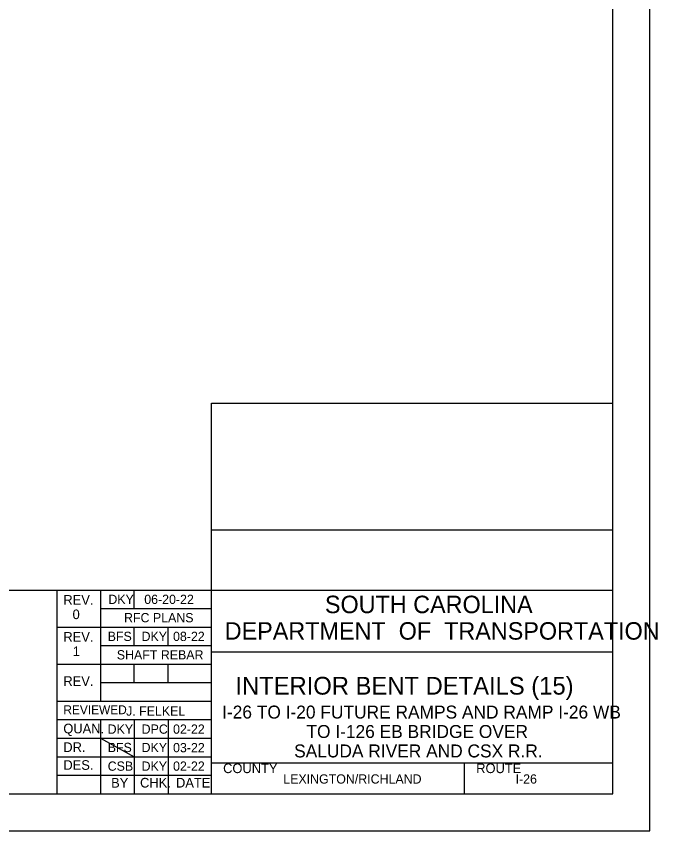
# Model space of a CAD drawing. Extents: x -149.6 to -53.3, y -21.7 to 37.
# Drawn here: x -76.41 to -53.32, y -21.66 to 7.67 of the extents above; entities that cross this region are included whole.
import ezdxf

# ---------------------------------------------------------------- set-up
doc = ezdxf.new("R2010")
doc.units = 0
for name, color, linetype in [('BR_BORDER LINES', 7, 'Continuous'), ('BR_TEXT', 7, 'Continuous'), ('Level 31', 7, 'Continuous')]:
    doc.layers.add(name, color=color, linetype=linetype)

msp = doc.modelspace()

# ---------------------------------------------------------------- linework, layer by layer
at = {"layer": 'BR_BORDER LINES'}
for p, q in [((-54.941, -20.327), (-54.941, 35.673)), ((-69.386, -20.327), (-69.386, -6.256)), ((-69.386, -6.256), (-54.941, -6.256)), ((-69.385, -10.828), (-54.941, -10.828)), ((-89.249, -12.993), (-74.941, -12.993)), ((-74.941, -20.327), (-74.941, -12.993)), ((-74.941, -12.993), (-54.941, -12.993)), ((-73.386, -12.993), (-73.386, -16.993)), ((-72.164, -13.66), (-72.164, -12.993)), ((-73.386, -13.66), (-69.386, -13.66)), ((-74.941, -14.326), (-69.386, -14.326)), ((-72.164, -14.993), (-72.164, -14.326)), ((-70.941, -14.993), (-70.941, -14.326)), ((-73.386, -14.993), (-69.386, -14.993)), ((-69.386, -15.215), (-69.386, -15.215)), ((-69.386, -15.215), (-54.94, -15.215)), ((-74.941, -15.66), (-69.386, -15.66)), ((-72.164, -16.326), (-72.164, -15.66)), ((-70.941, -16.326), (-70.941, -15.66)), ((-73.386, -16.326), (-69.386, -16.326)), ((-74.941, -16.993), (-69.386, -16.993)), ((-74.941, -17.66), (-69.386, -17.66)), ((-73.386, -17.66), (-73.386, -20.327)), ((-72.164, -17.66), (-72.164, -20.327)), ((-70.941, -17.66), (-70.941, -20.327)), ((-74.941, -18.327), (-69.386, -18.327)), ((-74.941, -18.993), (-69.386, -18.993)), ((-69.386, -19.215), (-54.941, -19.215)), ((-69.125, -19.215), (-54.941, -19.215)), ((-60.274, -20.327), (-60.274, -19.215)), ((-74.941, -19.66), (-69.386, -19.66)), ((-144.717, -20.327), (-54.941, -20.327))]:
    msp.add_line(p, q, dxfattribs=at)
at = {"layer": 'Level 31'}
for p, q in [((-62.162, -16.389), (-62.162, -16.389)), ((-73.386, -18.327), (-72.164, -18.993))]:
    msp.add_line(p, q, dxfattribs=at)
msp.add_lwpolyline([(-149.606, -21.66), (-53.606, -21.66), (-53.606, 37.007), (-149.606, 37.007)], close=True, dxfattribs=at)

# ---------------------------------------------------------------- texts
at = {"layer": 'BR_TEXT'}
for s, height, p in [('REV.', 0.3467, (-74.716, -13.519)), ('DKY', 0.3333, (-73.097, -13.493)), ('06-20-22', 0.3333, (-71.805, -13.493)), ('SOUTH CAROLINA', 0.62899, (-65.301, -13.824)), ('0', 0.347, (-74.385, -14.039)), ('RFC PLANS', 0.3333, (-72.533, -14.153)), ('DEPARTMENT  OF  TRANSPORTATION', 0.62899, (-68.908, -14.778)), ('REV.', 0.3467, (-74.716, -14.852)), ('BFS', 0.3333, (-73.122, -14.827)), ('DKY', 0.3333, (-71.902, -14.827)), ('08-22', 0.3333, (-70.769, -14.827)), ('1', 0.347, (-74.38, -15.372)), ('SHAFT REBAR', 0.33333, (-72.793, -15.491)), ('REV.', 0.3467, (-74.716, -16.445)), ('INTERIOR BENT DETAILS (15)', 0.64001, (-68.525, -16.758)), ('REVIEWED', 0.32, (-74.717, -17.464)), ('J. FELKEL', 0.3333, (-72.46, -17.515)), ('I-26 TO I-20 FUTURE RAMPS AND RAMP I-26 WB', 0.46667, (-69.003, -17.62)), ('QUAN.', 0.3467, (-74.719, -18.153)), ('DKY', 0.3333, (-73.123, -18.167)), ('DPC', 0.3333, (-71.899, -18.167)), ('02-22', 0.3333, (-70.768, -18.167)), ('TO I-126 EB BRIDGE OVER', 0.46667, (-65.968, -18.32)), ('DR.', 0.3467, (-74.719, -18.824)), ('BFS', 0.3333, (-73.121, -18.828)), ('DKY', 0.3333, (-71.901, -18.828)), ('03-22', 0.3333, (-70.768, -18.834)), ('SALUDA RIVER AND CSX R.R.', 0.46667, (-66.41, -19.02)), ('DES.', 0.3467, (-74.716, -19.467)), ('CSB', 0.3333, (-73.121, -19.5)), ('DKY', 0.3333, (-71.901, -19.5)), ('02-22', 0.3333, (-70.768, -19.5)), ('COUNTY', 0.3467, (-68.966, -19.585)), ('ROUTE', 0.3467, (-59.855, -19.585)), ('LEXINGTON/RICHLAND', 0.33332, (-66.801, -19.963)), ('I-26', 0.3333, (-58.438, -19.963)), ('BY', 0.3467, (-72.998, -20.108)), ('CHK.', 0.3467, (-71.956, -20.104)), ('DATE', 0.3467, (-70.662, -20.104))]:
    msp.add_text(s, height=height, dxfattribs=at).set_placement(p)

doc.saveas('drawing.dxf')
